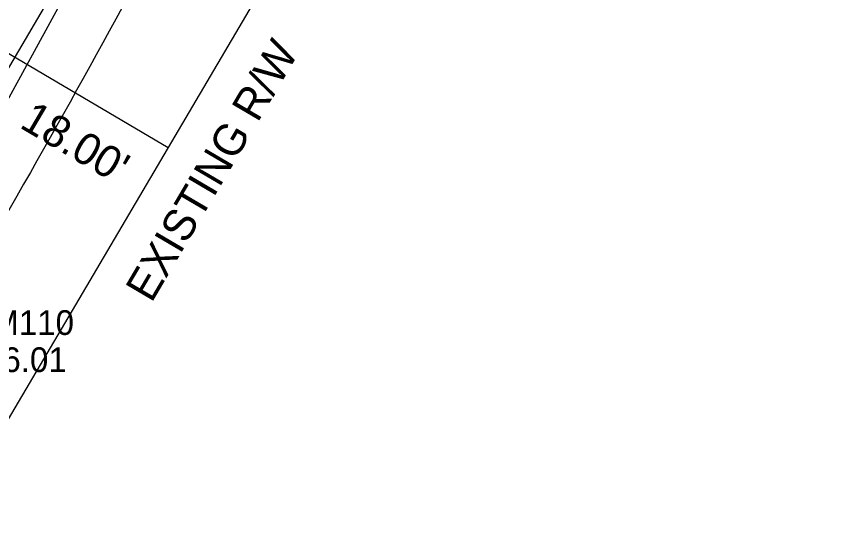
# Model space of a CAD drawing. Extents: x 1435573 to 1437263, y 981340 to 982884.
# Drawn here: x 1436138.2 to 1436220.8, y 982245.5 to 982298.4 of the extents above; entities that cross this region are included whole.
import ezdxf

# ---------------------------------------------------------------- set-up
doc = ezdxf.new("R2010")
doc.units = 0
for name, color, linetype in [('Exist Horizontal Alignment', 7, 'Continuous'), ('Exist Horizontal Baseline Alignment', 7, 'Continuous'), ('Exist Right of Way Line', 7, 'Continuous'), ('Exist Right of Way Line Text', 7, 'Continuous'), ('Exist Right of Way Width CELL', 7, 'Continuous'), ('Exist Roads EOP', 7, 'Continuous'), ('Exist Roads EOP Cogo Elevation', 7, 'Continuous'), ('Exist Roads EOP Cogo Number', 7, 'Continuous')]:
    doc.layers.add(name, color=color, linetype=linetype)

msp = doc.modelspace()

# ---------------------------------------------------------------- linework, layer by layer
at = {"layer": 'Exist Horizontal Alignment'}
msp.add_line((1436018.303, 982090.664), (1436160.981, 982333.125), dxfattribs=at)
at = {"layer": 'Exist Horizontal Baseline Alignment'}
msp.add_line((1435840.714, 981747.053), (1436220.786, 982442.589), dxfattribs=at)
at = {"layer": 'Exist Right of Way Line'}
msp.add_line((1436033.817, 982081.535), (1436176.494, 982323.996), dxfattribs=at)
at = {"layer": 'Exist Right of Way Width CELL'}
msp.add_line((1436153.596, 982285.083), (1436131.528, 982298.069), dxfattribs=at)
at = {"layer": 'Exist Roads EOP'}
for points in [[(1436168.247, 982354.253), (1436159.59, 982341.509), (1436138.871, 982307.915), (1436116.449, 982270.706), (1436094.594, 982234.299), (1436072.388, 982197.464), (1436049.682, 982158.518), (1436026.601, 982119.741), (1436003.228, 982078.86), (1435983.985, 982044.686), (1435963.778, 982007.011), (1435943.646, 981966.84), (1435922.148, 981922.092), (1435903.519, 981881.226), (1435884.45, 981840.589), (1435866.402, 981798.515)], [(1436177.116, 982349.863), (1436168.844, 982336.177), (1436150.231, 982301.677), (1436128.75, 982263.641), (1436107.214, 982226.88), (1436085.56, 982190.229), (1436062.44, 982151.3), (1436039.525, 982112.339), (1436015.808, 982071.467), (1435996.746, 982037.938), (1435976.483, 982000.314), (1435956.498, 981960.396), (1435935.191, 981915.993), (1435916.412, 981875.423), (1435898.23, 981835.836), (1435879.289, 981793.083)]]:
    msp.add_spline(points, degree=3, dxfattribs=at)

# ---------------------------------------------------------------- texts
at = {"layer": 'Exist Right of Way Line Text'}
msp.add_text('EXISTING R/W', height=3.2, rotation=59.52518, dxfattribs=at).set_placement((1436151.9, 982269.304))
at = {"layer": 'Exist Right of Way Width CELL'}
msp.add_text("18.00'", height=3.2, rotation=329.52518, dxfattribs=at).set_placement((1436138.447, 982287.184))
at = {"layer": 'Exist Roads EOP Cogo Elevation'}
msp.add_text('1356.01', height=2.5, dxfattribs=at).set_placement((1436131.25, 982262.391))
at = {"layer": 'Exist Roads EOP Cogo Number'}
msp.add_text('DTM110', height=2.5, dxfattribs=at).set_placement((1436131.25, 982266.141))

doc.saveas('drawing.dxf')
